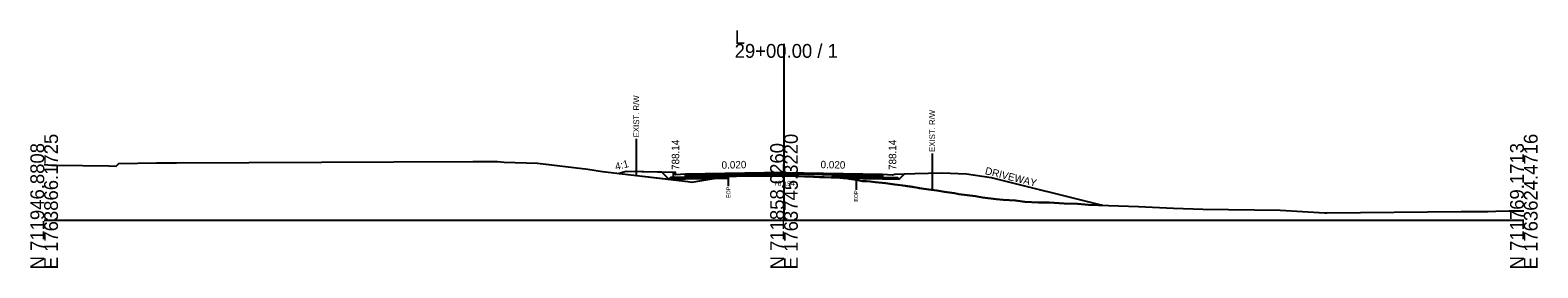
# Model space of a CAD drawing. Extents: x -26 to 5303, y -10 to 9578.
# Drawn here: x 997.2 to 1302.8, y 8990.3 to 9038.5 of the extents above; entities that cross this region are included whole.
import ezdxf

# ---------------------------------------------------------------- set-up
doc = ezdxf.new("R2010")
doc.units = 0
for name, color, linetype in [('Default', 7, 'Continuous'), ('Exist CMT Pavement', 7, 'Continuous'), ('Exist Cross Section Cell', 7, 'Continuous'), ('Exist XS Ground Line', 7, 'Continuous'), ('Old_Level_10', 7, 'Continuous'), ('Old_Level_3', 7, 'Continuous'), ('Prop CMT Conc Surface', 7, 'Continuous'), ('Prop CMT Concrete Structures', 7, 'Continuous'), ('Prop CMT Pvmt Course 1', 7, 'Continuous'), ('Prop CMT Pvmt Course 1 CG', 7, 'Continuous'), ('Prop CMT Pvmt Course 2', 7, 'Continuous'), ('Prop CMT Pvmt Course 3', 7, 'Continuous'), ('Prop CMT Pvmt Surface', 7, 'Continuous'), ('Prop CMT Slope Grass', 7, 'Continuous'), ('Prop CMT Subgrade Earthwork', 7, 'Continuous'), ('Prop XS Earthwork Shape', 7, 'Continuous'), ('Prop XS Hydro Elevations', 7, 'Continuous'), ('Prop XS SE Text', 7, 'Continuous'), ('Prop XS Side Slope Text', 7, 'Continuous'), ('Prop XS Wedging', 7, 'Continuous')]:
    doc.layers.add(name, color=color, linetype=linetype)

msp = doc.modelspace()

# ---------------------------------------------------------------- linework, layer by layer
at = {"layer": 'Exist CMT Pavement'}
msp.add_lwpolyline([(1138.71, 9008.89), (1139.88, 9008.91), (1140.34, 9008.92), (1141.67, 9008.93), (1142.64, 9008.94), (1143.45, 9008.94), (1144.56, 9008.94), (1145.24, 9008.94), (1145.75, 9008.94), (1147.03, 9008.95), (1148.85, 9008.95), (1150.48, 9008.93), (1150.83, 9008.93), (1152.39, 9008.89), (1153, 9008.87), (1155.05, 9008.79), (1157.22, 9008.71), (1157.76, 9008.69), (1158.16, 9008.68), (1159.55, 9008.64), (1161.33, 9008.57), (1161.97, 9008.54)], dxfattribs=at)
at = {"layer": 'Exist Cross Section Cell'}
for p, q in [((1150, 9000), (1150, 9035.68)), ((1000, 9000), (1150, 9000)), ((1150, 9000), (1300, 9000))]:
    msp.add_line(p, q, dxfattribs=at)
at = {"layer": 'Exist XS Ground Line'}
msp.add_lwpolyline([(1000, 9011.27), (1001.5, 9011.15), (1002.51, 9011.11), (1013.12, 9011), (1014.62, 9010.93), (1015.12, 9011.43), (1022.8, 9011.57), (1024.74, 9011.59), (1026.83, 9011.62), (1070.88, 9011.82), (1086.94, 9011.89), (1087.91, 9011.89), (1091.94, 9011.89), (1093.24, 9011.74), (1100.03, 9011.49), (1110.24, 9010.32), (1113.23, 9009.86), (1130.48, 9007.82), (1131.29, 9007.65), (1132.54, 9007.9), (1138.71, 9008.89), (1139.88, 9008.91), (1140.34, 9008.92), (1141.67, 9008.93), (1142.64, 9008.94), (1144.56, 9008.94), (1145.24, 9008.94), (1145.75, 9008.94), (1147.03, 9008.95), (1148.85, 9008.95), (1150.83, 9008.93), (1152.39, 9008.89), (1153, 9008.87), (1154.18, 9008.82), (1155.05, 9008.79), (1155.97, 9008.76), (1157.22, 9008.71), (1157.76, 9008.69), (1158.16, 9008.68), (1159.55, 9008.64), (1161.33, 9008.57), (1161.97, 9008.54), (1162.53, 9008.46), (1163.12, 9008.38), (1163.69, 9008.29), (1164.62, 9008.15), (1165.22, 9008.03), (1165.85, 9007.87), (1166.7, 9007.85), (1167.47, 9007.8), (1168.49, 9007.68), (1169.88, 9007.54), (1170.57, 9007.47), (1172.48, 9007.22), (1173.67, 9007.06), (1174.1, 9007), (1176.78, 9006.57), (1177.43, 9006.47), (1178.32, 9006.35), (1179.88, 9006.13), (1181.01, 9005.96), (1182.54, 9005.72), (1182.98, 9005.66), (1184.58, 9005.46), (1185.46, 9005.21), (1187.16, 9005.06), (1188.82, 9004.83), (1190.23, 9004.59), (1193, 9004.24), (1194.46, 9004.12), (1196.94, 9003.95), (1198.81, 9003.71), (1201.61, 9003.55), (1203.77, 9003.53), (1206.77, 9003.32), (1209.5, 9003.26), (1211.74, 9003.09), (1221.9, 9002.75), (1228.97, 9002.41), (1234.94, 9002.17), (1250.6, 9001.97), (1259.68, 9001.47), (1260.03, 9001.48), (1287.26, 9001.73), (1289.13, 9001.73), (1290.81, 9001.74), (1292.69, 9001.76), (1294.3, 9001.79), (1297.03, 9001.84), (1300, 9001.89)], dxfattribs=at)
at = {"layer": 'Old_Level_10'}
for p, q in [((1120.04, 9016.46), (1120.04, 9009.05)), ((1180.04, 9013.51), (1180.04, 9006.1)), ((1138.71, 9008.89), (1138.71, 9006.84)), ((1164.62, 9008.15), (1164.62, 9006.1))]:
    msp.add_line(p, q, dxfattribs=at)
at = {"layer": 'Prop CMT Conc Surface'}
for points in [[(1128, 9009.14), (1128, 9009.64), (1127.5, 9009.64)], [(1130, 9009.26), (1128, 9009.14)], [(1170, 9009.26), (1172, 9009.14)]]:
    msp.add_lwpolyline(points, dxfattribs=at)
at = {"layer": 'Prop CMT Concrete Structures'}
for points in [[(1130, 9009.26), (1128, 9009.14), (1128, 9009.64), (1127.5, 9009.64)], [(1127.5, 9009.64), (1127.5, 9008.62), (1130, 9008.67)], [(1130, 9008.67), (1130, 9009.26)]]:
    msp.add_lwpolyline(points, dxfattribs=at)
at = {"layer": 'Prop CMT Pvmt Course 1'}
for points in [[(1150, 9009.66), (1130, 9009.26)], [(1130, 9009.26), (1130, 9009.01)], [(1130, 9009.01), (1138.71, 9009.18)], [(1138.71, 9009.18), (1150, 9009.41)], [(1138.71, 9009.18), (1138.71, 9009.18)], [(1150, 9009.41), (1150, 9009.66)], [(1150, 9009.66), (1170, 9009.26)], [(1150, 9009.41), (1150, 9009.41), (1150, 9009.41)], [(1161.97, 9009.17), (1150, 9009.41)], [(1170, 9009.01), (1161.97, 9009.17)], [(1161.97, 9009.17), (1161.97, 9009.17)], [(1170, 9009.26), (1170, 9009.01)]]:
    msp.add_lwpolyline(points, dxfattribs=at)
at = {"layer": 'Prop CMT Pvmt Course 1 CG'}
for points in [[(1130, 9008.67), (1127, 9008.61), (1126.66, 9008.27)], [(1130, 9008.34), (1130, 9008.67)], [(1170, 9008.67), (1173, 9008.61), (1173.34, 9008.27)], [(1170, 9008.34), (1170, 9008.67)], [(1126.66, 9008.27), (1130, 9008.34)], [(1173.34, 9008.27), (1170, 9008.34)]]:
    msp.add_lwpolyline(points, dxfattribs=at)
at = {"layer": 'Prop CMT Pvmt Course 2'}
for points in [[(1138.71, 9009.18), (1130, 9009.01)], [(1130, 9009.01), (1130, 9008.67)], [(1130, 9008.67), (1138.71, 9008.85)], [(1138.71, 9008.85), (1138.71, 9009.18)], [(1161.97, 9008.83), (1161.97, 9009.17)], [(1161.97, 9009.17), (1170, 9009.01)], [(1170, 9008.67), (1161.97, 9008.83)], [(1170, 9009.01), (1170, 9008.67)]]:
    msp.add_lwpolyline(points, dxfattribs=at)
at = {"layer": 'Prop CMT Pvmt Course 3'}
for points in [[(1138.71, 9008.85), (1130, 9008.67)], [(1130, 9008.67), (1130, 9008.34)], [(1130, 9008.34), (1138.71, 9008.51)], [(1138.71, 9008.51), (1138.71, 9008.85)], [(1161.97, 9008.83), (1170, 9008.67)], [(1161.97, 9008.5), (1161.97, 9008.83)], [(1170, 9008.34), (1161.97, 9008.5)], [(1170, 9008.67), (1170, 9008.34)]]:
    msp.add_lwpolyline(points, dxfattribs=at)
at = {"layer": 'Prop CMT Pvmt Surface'}
for p, q in [((1170, 9009.26), (1172, 9009.14)), ((1172, 9009.14), (1172.5, 9009.3)), ((1172.5, 9009.3), (1176.5, 9009.46)), ((1176.5, 9009.46), (1182, 9009.57)), ((1182, 9009.57), (1187, 9009.37)), ((1187, 9009.37), (1192, 9008.62)), ((1192, 9008.62), (1214.51, 9003))]:
    msp.add_line(p, q, dxfattribs=at)
for points in [[(1150, 9009.66), (1130, 9009.26)], [(1150, 9009.66), (1170, 9009.26)]]:
    msp.add_lwpolyline(points, dxfattribs=at)
at = {"layer": 'Prop CMT Slope Grass'}
msp.add_lwpolyline([(1127.5, 9009.64), (1118, 9009.83), (1116.55, 9009.46)], dxfattribs=at)
at = {"layer": 'Prop CMT Subgrade Earthwork'}
for p, q in [((1138.71, 9008.51), (1138.71, 9008.89)), ((1161.97, 9008.5), (1161.97, 9008.54))]:
    msp.add_line(p, q, dxfattribs=at)
for points in [[(1130, 9008.34), (1126.66, 9008.27), (1125.25, 9009.68)], [(1138.71, 9008.51), (1130, 9008.34)], [(1161.97, 9008.5), (1170, 9008.34)], [(1170, 9008.34), (1173.34, 9008.27), (1174.45, 9009.38)]]:
    msp.add_lwpolyline(points, dxfattribs=at)
at = {"layer": 'Prop XS Earthwork Shape'}
for points in [[(1118, 9009.83), (1116.55, 9009.46), (1126.66, 9008.27), (1125.25, 9009.68)], [(1126.66, 9008.27), (1130.48, 9007.82), (1131.29, 9007.65), (1132.54, 9007.9), (1136.02, 9008.46), (1130, 9008.34)], [(1138.71, 9008.51), (1138.71, 9008.89), (1136.02, 9008.46)], [(1161.97, 9008.5), (1162.31, 9008.49), (1161.97, 9008.54)], [(1173.34, 9008.27), (1174.45, 9009.38), (1176.5, 9009.46), (1182, 9009.57), (1187, 9009.37), (1192, 9008.62), (1214.51, 9003), (1211.74, 9003.09), (1209.5, 9003.26), (1206.77, 9003.32), (1203.77, 9003.53), (1201.61, 9003.55), (1198.81, 9003.71), (1196.94, 9003.95), (1194.46, 9004.12), (1193, 9004.24), (1190.23, 9004.59), (1188.82, 9004.83), (1187.16, 9005.06), (1185.46, 9005.21), (1184.58, 9005.46), (1182.98, 9005.66), (1182.54, 9005.72), (1181.01, 9005.96), (1179.88, 9006.13), (1178.32, 9006.35), (1176.78, 9006.57), (1175.64, 9006.76), (1174.1, 9007), (1172.48, 9007.22), (1170.57, 9007.47), (1169.88, 9007.54), (1168.49, 9007.68), (1167.47, 9007.8), (1166.7, 9007.85), (1165.85, 9007.87), (1165.22, 9008.03), (1164.62, 9008.15), (1163.69, 9008.29), (1163.12, 9008.38), (1162.53, 9008.46), (1162.31, 9008.49), (1170, 9008.34)]]:
    msp.add_lwpolyline(points, close=True, dxfattribs=at)
at = {"layer": 'Prop XS Wedging'}
for points in [[(1138.71, 9008.89), (1138.71, 9009.18), (1139.88, 9009.2), (1140.34, 9009.21), (1141.67, 9009.24), (1142.64, 9009.26), (1143.45, 9009.28), (1144.56, 9009.3), (1145.24, 9009.31), (1145.75, 9009.32), (1147.03, 9009.35), (1148.85, 9009.38), (1150, 9009.41), (1150.48, 9009.4), (1150.83, 9009.39), (1152.39, 9009.36), (1153, 9009.35), (1155.05, 9009.3), (1157.22, 9009.26), (1157.76, 9009.25), (1158.16, 9009.24), (1159.55, 9009.22), (1161.33, 9009.18), (1161.97, 9009.17), (1161.97, 9008.54), (1161.33, 9008.57), (1159.55, 9008.64), (1158.16, 9008.68), (1157.76, 9008.69), (1157.22, 9008.71), (1155.05, 9008.79), (1153, 9008.87), (1152.39, 9008.89), (1150.83, 9008.93), (1150.48, 9008.93), (1150, 9008.94), (1148.85, 9008.95), (1147.03, 9008.95), (1145.75, 9008.94), (1145.24, 9008.94), (1144.56, 9008.94), (1143.45, 9008.94), (1142.64, 9008.93), (1141.67, 9008.93), (1140.34, 9008.92), (1139.88, 9008.91)], [(1159.56, 9008.64), (1159.8, 9008.88), (1161.33, 9008.85), (1161.97, 9008.84), (1161.97, 9008.54), (1161.33, 9008.57)]]:
    msp.add_lwpolyline(points, close=True, dxfattribs=at)

# ---------------------------------------------------------------- texts
at = {"layer": 'Default'}
msp.add_text('-', height=0.0001, dxfattribs=at).set_placement((1000, 9000))
at = {"layer": 'Exist Cross Section Cell'}
for s, p in [('L', (1140, 9035.68)), ('29+00.00 / 1', (1140, 9032.88))]:
    msp.add_text(s, height=2.8, dxfattribs=at).set_placement(p)
for s, p in [('N 711946.8808', (1000, 8990)), ('E 1763866.1725', (1002.8, 8990)), ('N 711858.0260', (1150, 8990)), ('E 1763745.3220', (1152.8, 8990)), ('N 711769.1713', (1300, 8990)), ('E 1763624.4716', (1302.8, 8990))]:
    msp.add_text(s, height=2.8, rotation=90, dxfattribs=at).set_placement(p)
at = {"layer": 'Old_Level_10'}
for s, height, p in [('EXIST. R/W', 1.181, (1120.63, 9016.76)), ('EXIST. R/W', 1.181, (1180.63, 9013.81)), ('EOP', 0.787, (1139.11, 9004.44)), ('EOP', 0.787, (1165.01, 9003.7))]:
    msp.add_text(s, height=height, rotation=90, dxfattribs=at).set_placement(p)
at = {"layer": 'Old_Level_3'}
msp.add_text('787.94', height=1, dxfattribs=at).set_placement((1147.95, 9006.94))
at = {"layer": 'Prop XS Hydro Elevations'}
for p in [(1128.75, 9010.14), (1172.75, 9010.14)]:
    msp.add_text('788.14', height=1.5, rotation=90, dxfattribs=at).set_placement(p)
at = {"layer": 'Prop XS SE Text'}
for rotation, p in [(1.1458, (1137.36, 9010.4)), (358.8542, (1157.4, 9010.51))]:
    msp.add_text('0.020', height=1.5, rotation=rotation, dxfattribs=at).set_placement(p)
at = {"layer": 'Prop XS Side Slope Text'}
for s, rotation, p in [('4:1', 14.0362, (1115.94, 9010.08)), ('DRIVEWAY', 345.9638, (1190.64, 9009.32))]:
    msp.add_text(s, height=1.5, rotation=rotation, dxfattribs=at).set_placement(p)

doc.saveas('drawing.dxf')
